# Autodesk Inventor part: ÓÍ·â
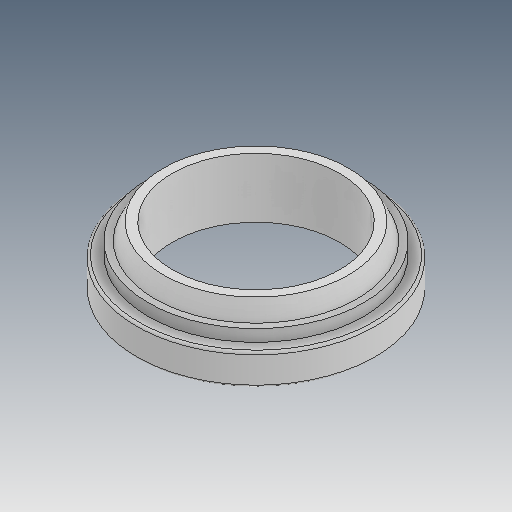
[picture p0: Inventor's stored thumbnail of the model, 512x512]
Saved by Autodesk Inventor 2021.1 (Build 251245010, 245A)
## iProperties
Created: 2013-04
Part Number: ÓÍ·â
Material: Ogólny
Document SubType Name: Modeling
Designer: user
Density: 1 g/cm^3
Appearance: Domyślna
Author: user
Revision Number: ÈÎºÎ
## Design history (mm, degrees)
feature "Ðý×ª1"
node "Bryła1"
